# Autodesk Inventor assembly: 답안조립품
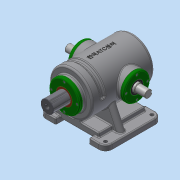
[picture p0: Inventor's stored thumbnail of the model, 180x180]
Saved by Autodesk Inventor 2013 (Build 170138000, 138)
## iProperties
Created: 2018-06
Part Number: 답안조립품
Document SubType Name: Assembly
Designer: Administrator
Mass: 8560.47 g
Surface Area: 4294.68 cm^2
Volume: 2307.06 cm^3
Density: 3.71055 g/cm^3
Author: Administrator
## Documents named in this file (13)
- C:\Users\Administrator\Desktop\380628V1003\답안조립품.iam
- C:\Users\Administrator\Desktop\380628V1003\본체.ipt
- C:\Users\Administrator\Desktop\380628V1003\가변스프링.ipt
- C:\Users\Administrator\Desktop\380628V1003\베어링 6205.ipt
- 베어링 6205.ipt
- C:\Users\Administrator\Desktop\380628V1003\볼트 M4.ipt
- C:\Users\Administrator\Desktop\380628V1003\부시.ipt
- C:\Users\Administrator\Desktop\380628V1003\슬라이드 커버.ipt
- C:\Users\Administrator\Desktop\380628V1003\슬라이드.ipt
- C:\Users\Administrator\Desktop\380628V1003\오일실.ipt
- 오일실.ipt
- C:\Users\Administrator\Desktop\380628V1003\축 커버.ipt
- C:\Users\Administrator\Desktop\380628V1003\편심축.ipt
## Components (1 placed, 1 different names)
1. 가변스프링:1
